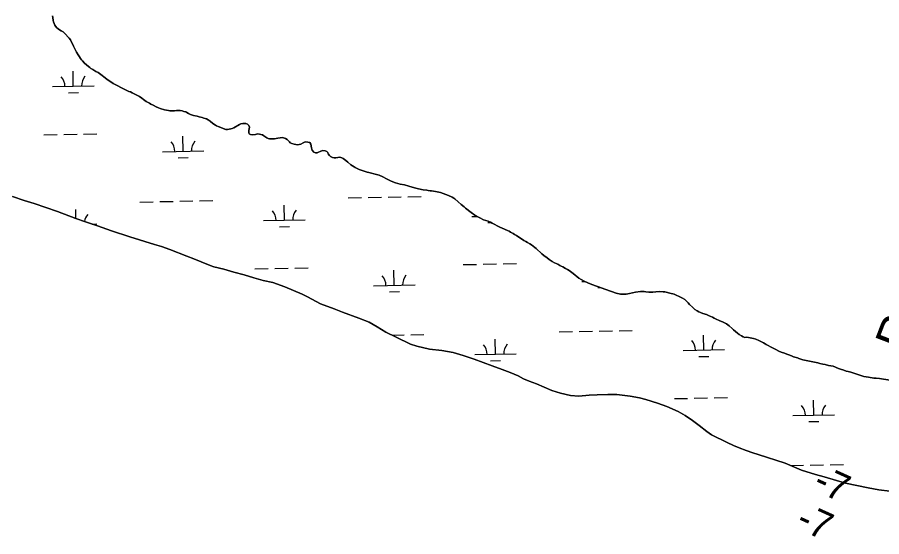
# Model space of a CAD drawing. Extents: x 3989314 to 4027622, y 243956 to 270014.
# Drawn here: x 4016981 to 4019063, y 256390 to 257641 of the extents above; entities that cross this region are included whole.
import ezdxf

# ---------------------------------------------------------------- set-up
doc = ezdxf.new("R2010")
doc.units = 0
for name, color, linetype in [('V-RIVR-EDGE', 7, 'Continuous'), ('V-RIVR-RANG', 7, 'Continuous'), ('V-RIVR-RANG-IDEN', 7, 'Continuous'), ('V-WETL-SWMP', 7, 'Continuous')]:
    doc.layers.add(name, color=color, linetype=linetype)

msp = doc.modelspace()

# ---------------------------------------------------------------- linework, layer by layer
at = {"layer": 'V-RIVR-EDGE'}
for points in [[(4017495.6, 257372.1), (4017487.8, 257370.7), (4017483.6, 257371), (4017465.3, 257377.9), (4017460.9, 257379.8), (4017458.2, 257381.2), (4017452.3, 257385.4), (4017446.1, 257390.7), (4017441.2, 257394.2), (4017436.7, 257396.4), (4017430.7, 257398.5), (4017426.4, 257399.8), (4017419.3, 257401.4), (4017414.5, 257402.7), (4017405.8, 257404.7), (4017398.5, 257406.9), (4017393.6, 257409.3), (4017389.9, 257411.5), (4017386.7, 257413), (4017382.6, 257414.5), (4017378.2, 257415.6), (4017373.6, 257416.4), (4017368.7, 257416.5), (4017364.7, 257416.2), (4017359.9, 257416.1), (4017356.3, 257415.8), (4017348.7, 257416), (4017345.6, 257416.3), (4017336, 257418.2), (4017325, 257421.6), (4017321, 257423.1), (4017315.9, 257425.7), (4017308.2, 257429.1), (4017302.9, 257431.8), (4017299.2, 257433.9), (4017296.1, 257436), (4017291.2, 257438.5), (4017285.5, 257443), (4017281.4, 257445.9), (4017275.7, 257449.9), (4017270.6, 257453), (4017257.7, 257459.5), (4017253.9, 257461.2), (4017250, 257462.7), (4017244.9, 257465), (4017234, 257470.7), (4017220.5, 257477.2), (4017212.2, 257481.6), (4017203.8, 257487.6), (4017200.3, 257489.7), (4017197, 257492.4), (4017189.3, 257497.8), (4017185.8, 257500.7), (4017175.7, 257507.7), (4017170.6, 257510.6), (4017162.9, 257515.4), (4017158.4, 257517.9), (4017155.5, 257519.8), (4017152.3, 257522.3), (4017143.2, 257530.7), (4017138.6, 257535.8), (4017136, 257538.2), (4017133, 257542.1), (4017131.1, 257545.7), (4017127.8, 257550.4), (4017124, 257557.1), (4017116.8, 257571.6), (4017109.2, 257586.4), (4017106, 257591), (4017094.9, 257603.1), (4017091.8, 257605.8), (4017087.1, 257608.7), (4017083.2, 257610.4), (4017079.3, 257612.9), (4017075.2, 257616.4), (4017071.3, 257621.8), (4017068.6, 257630.3), (4017067.8, 257633.3), (4017066.6, 257640.1), (4017066.2, 257644.9)], [(4018028.9, 257207.6), (4018019.9, 257212.3), (4018007.2, 257216.8), (4018000.3, 257218.8), (4017988.4, 257221.5), (4017978.9, 257223.1), (4017975.5, 257223.4), (4017970.8, 257224.1), (4017967.6, 257224.8), (4017958.9, 257225.6), (4017947.4, 257227.9), (4017937.9, 257230.6), (4017924.6, 257234.7), (4017913.9, 257237.4), (4017903.2, 257239.1), (4017892, 257242.2), (4017881.5, 257246.2), (4017877, 257248.7), (4017873.6, 257250.2), (4017870.3, 257252.3), (4017861.9, 257256.9), (4017852.8, 257260.7), (4017846.1, 257262.9), (4017827.7, 257267.2), (4017824.1, 257267.9), (4017821.2, 257269), (4017816.4, 257270.3), (4017804.2, 257274.8), (4017795.1, 257279), (4017792.2, 257280.7), (4017784.8, 257286.1), (4017777.1, 257292.1), (4017772.1, 257296.4), (4017766.4, 257300.7), (4017762.7, 257302.6), (4017758.3, 257303.9), (4017753.1, 257303.6), (4017748.3, 257303), (4017744.4, 257302.9), (4017740.6, 257303.6), (4017735.9, 257305.5), (4017733.1, 257308), (4017730.3, 257312), (4017728.9, 257315.1), (4017726.8, 257318.1), (4017722.9, 257319.8), (4017716.5, 257320), (4017710.9, 257318.1), (4017706.5, 257315.9), (4017703.4, 257314.7), (4017699.6, 257314.4), (4017695.3, 257316.3), (4017691.7, 257321), (4017690.5, 257323.8), (4017690, 257326.8), (4017688.1, 257335.7), (4017685.4, 257339.3), (4017680.8, 257340.4), (4017676.4, 257340.8), (4017673, 257340), (4017669.6, 257338.9), (4017663.8, 257335.7), (4017659.9, 257334.4), (4017656.1, 257333.9), (4017648.4, 257335.3), (4017642.7, 257336.9), (4017638.7, 257338.8), (4017636.4, 257340.8), (4017631.4, 257346.7), (4017627.1, 257349.4), (4017622.5, 257351), (4017619.6, 257351.4), (4017614, 257351), (4017608.9, 257349.9), (4017600.3, 257348.6), (4017591.8, 257348), (4017588.4, 257348.1), (4017585.4, 257349), (4017582.1, 257351), (4017575.2, 257356), (4017571.9, 257357.7), (4017568, 257359.2), (4017564.4, 257359.9), (4017559.8, 257360.2), (4017555, 257359.1), (4017548, 257357.9), (4017543.2, 257358.6), (4017539.9, 257360.1), (4017538.6, 257363.8), (4017538.9, 257368.7), (4017540.1, 257376.1), (4017539, 257380.3), (4017535.9, 257383.3), (4017531.8, 257385.3), (4017527.8, 257385.6), (4017524.4, 257385.4), (4017519.6, 257384.4), (4017516.4, 257382.9), (4017502.8, 257375.1), (4017498.6, 257373.2), (4017495.6, 257372.1)], [(4016969.7, 257209.2), (4016997.9, 257200.1), (4017022.1, 257193)], [(4018733.3, 256870.3), (4018729.6, 256871.8), (4018725.2, 256873.9), (4018719.8, 256877.3), (4018715.5, 256880.4), (4018706.1, 256888.8), (4018703.2, 256891.6), (4018696, 256898.2), (4018689.6, 256902.6), (4018684.6, 256905.3), (4018681.1, 256906.8), (4018671.9, 256911.4), (4018664.8, 256914.4), (4018659.5, 256916.9), (4018655.9, 256918.8), (4018647.3, 256922.6), (4018640.9, 256925.2), (4018632.7, 256928.2), (4018626.7, 256930.1), (4018622.6, 256931.8), (4018618.7, 256934.1), (4018613, 256937.7), (4018607.4, 256942.8), (4018600.4, 256949.8), (4018597.3, 256953.4), (4018594.9, 256955.9), (4018592.6, 256958.1), (4018588.9, 256961.2), (4018583.6, 256964.8), (4018578.7, 256967.3), (4018575.4, 256968.6), (4018568.1, 256971.9), (4018563, 256974.1), (4018553.1, 256976.9), (4018544.4, 256979.1), (4018541, 256979.8), (4018537, 256980.3), (4018526.9, 256980.6), (4018519.1, 256980.2), (4018511.7, 256979.6), (4018501.9, 256979.3), (4018494.8, 256979.9), (4018491, 256980.8), (4018482.3, 256981.2), (4018469.9, 256979.1), (4018456, 256976.1), (4018447.8, 256974.7), (4018441.8, 256974.1), (4018434.1, 256974.5), (4018423.4, 256977.2), (4018398.7, 256985.6), (4018378.4, 256993.1), (4018373.7, 256994.7), (4018360.6, 256999.6), (4018347.8, 257004.9), (4018339.2, 257009.5), (4018333.5, 257012.9), (4018320.2, 257024), (4018310.1, 257031.4), (4018306.2, 257033.9), (4018301.9, 257036.4), (4018295.2, 257040), (4018291.4, 257041.9), (4018287.9, 257043.4), (4018282.8, 257046.5), (4018275.1, 257050.1), (4018269.4, 257053), (4018262.6, 257057.6), (4018257.1, 257061.5), (4018249.7, 257067.5), (4018244.6, 257071.8), (4018231, 257084.3), (4018227.9, 257087), (4018219.7, 257093), (4018216, 257095.3), (4018209.9, 257098.4), (4018205.8, 257101.1), (4018201, 257103.6), (4018183.2, 257115.3), (4018178.9, 257117.8), (4018175.2, 257120.5), (4018169.1, 257123.6), (4018165.6, 257125.7), (4018162, 257127.4), (4018149.4, 257133.1), (4018143.5, 257135.5), (4018125.3, 257145.5), (4018121.1, 257147.6), (4018118.4, 257148.9), (4018115.2, 257149.8), (4018104.4, 257153.6), (4018095.1, 257157.9), (4018083.1, 257165), (4018074.7, 257171), (4018060.7, 257181.7), (4018057.2, 257185), (4018050.4, 257190.5), (4018043.2, 257196.9), (4018035, 257203.7), (4018032.4, 257205.6), (4018028.9, 257207.6)], [(4017022.1, 257193), (4017077.7, 257173.2), (4017122.1, 257156.3), (4017145.2, 257148.5), (4017174.6, 257139), (4017208, 257126.9), (4017252.4, 257112.4), (4017311.5, 257094.3), (4017328.7, 257088.8), (4017348.2, 257082.1), (4017389.4, 257065.5), (4017406.2, 257059.5), (4017423.9, 257052.2), (4017445.4, 257043.1), (4017454.5, 257039.9), (4017478.8, 257034.2), (4017502.4, 257027.6), (4017527.9, 257020.8), (4017551, 257013.6), (4017573.5, 257007.2), (4017596.5, 257002.2), (4017625.5, 256991.9), (4017667.1, 256974.2), (4017680.3, 256967.9), (4017711.1, 256951.3), (4017744.4, 256938.9), (4017764.3, 256930.8), (4017803.6, 256916.8), (4017828.8, 256907), (4017848.3, 256895.5), (4017869, 256882.8), (4017893.8, 256870.6), (4017928.4, 256854.1), (4017943.2, 256848.9), (4017974.3, 256842.3), (4018003.9, 256838.8), (4018031.3, 256833.6), (4018054.8, 256827), (4018081.3, 256817.8), (4018124.7, 256802.1), (4018149.2, 256793.4), (4018167.9, 256786.2), (4018187.6, 256777.9), (4018200.3, 256770.8), (4018213.7, 256765.2), (4018231.5, 256758.4), (4018268.3, 256742.5), (4018289.7, 256735.9), (4018313.6, 256730.3), (4018333.3, 256728.8), (4018358.5, 256730.9), (4018377.8, 256731.8), (4018403.9, 256732.7), (4018425, 256732.5), (4018457.4, 256729.1), (4018479.6, 256724.9), (4018495.3, 256720.9), (4018522.9, 256712.2), (4018545.8, 256703.6), (4018573, 256691.9), (4018589.4, 256681.9), (4018607.5, 256670.3), (4018623.9, 256658.3), (4018641.6, 256643.5), (4018652.9, 256635.4), (4018691.3, 256617.4), (4018705.9, 256609.9), (4018719.7, 256604.3), (4018736.4, 256598.3), (4018753, 256592.7), (4018765.7, 256588.8)], [(4018982.1, 256788.1), (4018977.4, 256789.3), (4018972.3, 256791.5), (4018964.3, 256793.6), (4018958.9, 256795.5), (4018945.9, 256800.7), (4018940.8, 256802.1), (4018935.3, 256803), (4018927, 256805.1), (4018921.7, 256806), (4018914.2, 256807.7), (4018909.1, 256809.1), (4018897.1, 256811.2), (4018881.5, 256814.6), (4018877.5, 256815.8), (4018873.2, 256816.7), (4018863.7, 256819.6), (4018860, 256821), (4018854.1, 256822.5), (4018850.7, 256823.6), (4018847.3, 256824.8), (4018842.1, 256827.3), (4018834.4, 256829.9), (4018828.8, 256832.3), (4018821, 256835.1), (4018815, 256837.4), (4018808, 256840.8), (4018803.1, 256843.4), (4018800.5, 256845.1), (4018784.9, 256853.5), (4018782.1, 256855.2), (4018778.4, 256857), (4018773.7, 256859.8), (4018767, 256863), (4018760, 256865.8), (4018754.7, 256867.6), (4018742.4, 256869.9), (4018738.2, 256870.5), (4018733.3, 256870.3)], [(4019082.6, 256767.4), (4019057.6, 256771), (4019049.9, 256771.8), (4019044.4, 256772.1), (4019031, 256774.4), (4019020.3, 256776.5), (4018989.1, 256786.6), (4018982.1, 256788.1)], [(4018765.7, 256588.8), (4018830.6, 256567.4), (4018870.3, 256550.4), (4018903.5, 256539.9), (4018924.3, 256534.4), (4018975.6, 256519.6), (4019030.2, 256508), (4019056, 256503.6), (4019082.7, 256500.1)]]:
    msp.add_lwpolyline(points, dxfattribs=at)
at = {"layer": 'V-WETL-SWMP'}
for p, q in [((4017116.1, 257475), (4017115.4, 257511)), ((4017066.1, 257474), (4017166.1, 257476)), ((4017104.4, 257459.3), (4017128.4, 257459.8)), ((4017045, 257358.1), (4017077, 257358.8)), ((4017093, 257359.1), (4017125, 257359.7)), ((4017141, 257360), (4017173, 257360.7)), ((4017380.7, 257318.4), (4017380, 257354.4)), ((4017330.7, 257317.4), (4017430.7, 257319.4)), ((4017369, 257302.7), (4017393, 257303.2)), ((4017276.3, 257196.2), (4017308.3, 257196.8)), ((4017324.3, 257197.2), (4017356.3, 257197.8)), ((4017372.3, 257198.1), (4017404.2, 257198.8)), ((4017420.2, 257199.1), (4017452.2, 257199.7)), ((4017778.1, 257206.2), (4017810.1, 257206.8)), ((4017826.1, 257207.2), (4017858.1, 257207.8)), ((4017874.1, 257208.1), (4017906.1, 257208.8)), ((4017922, 257209.1), (4017954, 257209.7)), ((4017122.4, 257156.2), (4017122, 257178.4)), ((4017624.5, 257152.4), (4017623.8, 257188.4)), ((4018076.3, 257161.4), (4018088.7, 257161.6)), ((4017161.7, 257143.2), (4017172.7, 257143.4)), ((4017574.5, 257151.4), (4017674.5, 257153.4)), ((4017612.8, 257136.7), (4017636.8, 257137.2)), ((4018114.6, 257146.7), (4018122.6, 257146.9)), ((4017553.4, 257035.5), (4017585.4, 257036.2)), ((4017601.4, 257036.5), (4017633.4, 257037.1)), ((4017649.4, 257037.4), (4017681.4, 257038.1)), ((4017889.1, 256995.8), (4017888.4, 257031.8)), ((4018055.2, 257045.5), (4018087.2, 257046.2)), ((4018103.2, 257046.5), (4018135.2, 257047.1)), ((4018151.2, 257047.4), (4018183.2, 257048.1)), ((4017839.1, 256994.8), (4017939.1, 256996.8)), ((4018341, 257004.8), (4018347.8, 257004.9)), ((4018379.3, 256990.1), (4018386.2, 256990.2)), ((4017877.4, 256980.1), (4017901.4, 256980.6)), ((4018286.5, 256883.6), (4018318.5, 256884.2)), ((4018334.5, 256884.6), (4018366.5, 256885.2)), ((4018382.5, 256885.5), (4018414.5, 256886.1)), ((4018430.5, 256886.5), (4018462.5, 256887.1)), ((4017883.7, 256875.6), (4017912.7, 256876.1)), ((4017928.7, 256876.5), (4017960.7, 256877.1)), ((4018133, 256829.8), (4018132.2, 256865.8)), ((4018634.8, 256839.8), (4018634.1, 256875.8)), ((4018083, 256828.8), (4018183, 256830.8)), ((4018584.8, 256838.8), (4018684.8, 256840.8)), ((4018623.1, 256824.1), (4018647.1, 256824.6)), ((4018121.3, 256814.1), (4018145.3, 256814.6)), ((4018563.7, 256722.9), (4018595.7, 256723.6)), ((4018611.7, 256723.9), (4018643.7, 256724.5)), ((4018659.7, 256724.8), (4018691.7, 256725.5)), ((4018899.4, 256683.2), (4018898.7, 256719.2)), ((4018849.4, 256682.2), (4018949.4, 256684.2)), ((4018887.7, 256667.5), (4018911.7, 256668)), ((4018843.4, 256562), (4018874.9, 256562.6)), ((4018890.9, 256562.9), (4018922.9, 256563.5)), ((4018938.9, 256563.9), (4018970.9, 256564.5))]:
    msp.add_line(p, q, dxfattribs=at)
for points in [[(4017066.2, 257644.9), (4017066.6, 257640.1), (4017067.9, 257633.3), (4017068.6, 257630.3), (4017071.3, 257621.8), (4017075.2, 257616.4), (4017079.3, 257612.9), (4017083.2, 257610.4), (4017087.1, 257608.7), (4017091.8, 257605.8), (4017094.9, 257603.1), (4017106, 257591), (4017109.2, 257586.4), (4017116.8, 257571.6), (4017124, 257557.1), (4017127.8, 257550.4), (4017131.1, 257545.7), (4017133, 257542.1), (4017136, 257538.2), (4017138.6, 257535.8), (4017143.2, 257530.7), (4017152.3, 257522.3), (4017155.5, 257519.8), (4017158.4, 257517.9), (4017162.9, 257515.4), (4017170.6, 257510.6), (4017175.7, 257507.7), (4017185.8, 257500.7), (4017189.3, 257497.8), (4017197, 257492.4), (4017200.3, 257489.7), (4017203.8, 257487.6), (4017212.2, 257481.6), (4017220.5, 257477.2), (4017234, 257470.7), (4017244.9, 257465), (4017250, 257462.7), (4017253.9, 257461.2), (4017257.7, 257459.5), (4017270.6, 257453), (4017275.7, 257449.9)], [(4017275.7, 257449.9), (4017281.4, 257445.9), (4017285.5, 257443), (4017291.2, 257438.5), (4017296.1, 257436), (4017299.2, 257433.9), (4017302.9, 257431.8), (4017308.2, 257429.1), (4017315.9, 257425.7), (4017321, 257423.1), (4017325, 257421.6), (4017336, 257418.2), (4017345.6, 257416.3), (4017348.7, 257416), (4017356.3, 257415.8), (4017359.9, 257416.1), (4017364.7, 257416.2), (4017368.7, 257416.5), (4017373.6, 257416.4), (4017378.2, 257415.6), (4017382.6, 257414.5), (4017386.7, 257413), (4017389.9, 257411.5), (4017393.6, 257409.3), (4017398.5, 257406.9), (4017405.8, 257404.7), (4017414.5, 257402.7), (4017419.3, 257401.4), (4017426.4, 257399.8), (4017430.7, 257398.5), (4017436.7, 257396.4), (4017441.2, 257394.2), (4017446.1, 257390.7), (4017452.3, 257385.4), (4017458.2, 257381.2), (4017460.9, 257379.8), (4017465.3, 257377.9), (4017483.6, 257371), (4017487.8, 257370.7), (4017495.6, 257372.1), (4017498.6, 257373.2), (4017502.8, 257375.1), (4017516.4, 257382.9), (4017519.6, 257384.4), (4017524.4, 257385.4), (4017527.8, 257385.6), (4017531.8, 257385.3), (4017535.9, 257383.3), (4017539, 257380.3), (4017540.1, 257376.1), (4017538.9, 257368.7), (4017538.6, 257363.8), (4017539.9, 257360.1), (4017543.2, 257358.6), (4017548, 257357.9), (4017555, 257359.1), (4017559.8, 257360.2), (4017564.4, 257359.9), (4017568, 257359.2), (4017571.9, 257357.7), (4017575.2, 257356), (4017582.1, 257351), (4017585.4, 257349), (4017588.4, 257348.1), (4017591.8, 257348), (4017600.3, 257348.6), (4017609, 257349.9), (4017614, 257351), (4017619.5, 257351.4), (4017622.5, 257351), (4017627.1, 257349.4), (4017631.4, 257346.7), (4017636.4, 257340.8), (4017638.7, 257338.8), (4017642.7, 257336.9), (4017648.4, 257335.3), (4017656.1, 257333.9), (4017659.9, 257334.4), (4017663.8, 257335.7), (4017669.6, 257338.9), (4017673, 257340), (4017676.4, 257340.8), (4017680.8, 257340.4), (4017685.4, 257339.3), (4017688.1, 257335.7), (4017690, 257326.8), (4017690.5, 257323.8), (4017691.7, 257321), (4017695.3, 257316.3), (4017699.6, 257314.4), (4017703.4, 257314.7), (4017706.5, 257315.9), (4017710.9, 257318.1), (4017716.5, 257320), (4017722.9, 257319.8), (4017726.8, 257318.1), (4017728.9, 257315.1), (4017730.3, 257312), (4017733.1, 257308), (4017735.9, 257305.5), (4017740.6, 257303.6)], [(4017740.6, 257303.6), (4017744.4, 257302.9), (4017748.3, 257303), (4017753.1, 257303.6), (4017758.3, 257303.9), (4017762.7, 257302.6), (4017766.4, 257300.7), (4017772.1, 257296.4), (4017777.1, 257292.1), (4017784.8, 257286.1), (4017792.2, 257280.7), (4017795.1, 257279), (4017804.2, 257274.8), (4017816.4, 257270.3), (4017821.2, 257269), (4017824.1, 257267.9), (4017827.7, 257267.2), (4017846.1, 257262.9), (4017852.8, 257260.7), (4017861.9, 257256.9), (4017870.3, 257252.3), (4017873.6, 257250.2), (4017877, 257248.7), (4017881.5, 257246.2), (4017892, 257242.2), (4017903.2, 257239.1), (4017913.9, 257237.4), (4017924.6, 257234.7), (4017937.9, 257230.6), (4017947.4, 257227.9), (4017958.9, 257225.6), (4017967.6, 257224.8), (4017970.8, 257224.1), (4017975.5, 257223.4), (4017978.9, 257223.1), (4017988.4, 257221.5), (4018000.3, 257218.8), (4018007.2, 257216.8), (4018019.9, 257212.3), (4018028.9, 257207.6), (4018032.4, 257205.6), (4018035, 257203.7), (4018043.2, 257196.9), (4018050.4, 257190.5), (4018057.2, 257185), (4018060.7, 257181.7), (4018074.7, 257171), (4018083.1, 257165), (4018095.1, 257157.9), (4018104.4, 257153.6), (4018115.2, 257149.8), (4018118.4, 257148.9), (4018121.1, 257147.6), (4018125.3, 257145.5), (4018143.5, 257135.5), (4018149.4, 257133.1), (4018162, 257127.4), (4018165.6, 257125.7), (4018169.1, 257123.6), (4018175.2, 257120.5), (4018178.9, 257117.8), (4018183.2, 257115.3), (4018201, 257103.6), (4018205.8, 257101.1), (4018209.9, 257098.4), (4018216, 257095.3), (4018219.7, 257093), (4018227.9, 257087), (4018231, 257084.3), (4018244.6, 257071.8), (4018249.7, 257067.5), (4018257.1, 257061.5), (4018262.6, 257057.6), (4018269.4, 257053), (4018275.1, 257050.1), (4018282.8, 257046.5), (4018287.9, 257043.4), (4018291.4, 257041.9), (4018295.2, 257040), (4018301.9, 257036.4), (4018306.2, 257033.9), (4018310.1, 257031.4), (4018320.2, 257024), (4018333.5, 257012.9), (4018339.2, 257009.5), (4018347.8, 257004.9), (4018360.6, 256999.6), (4018373.7, 256994.7), (4018378.4, 256993.1), (4018398.7, 256985.6), (4018423.4, 256977.2), (4018434.1, 256974.5), (4018441.8, 256974.1), (4018447.8, 256974.7), (4018456, 256976.1), (4018469.9, 256979.1), (4018482.3, 256981.2), (4018491, 256980.8), (4018494.8, 256979.9), (4018501.9, 256979.3), (4018511.7, 256979.6)], [(4019082.7, 256500.1), (4019056, 256503.6), (4019030.2, 256508), (4018975.6, 256519.6), (4018924.3, 256534.4), (4018903.5, 256539.9), (4018870.3, 256550.4), (4018830.6, 256567.4), (4018765.7, 256588.8), (4018753, 256592.7), (4018736.4, 256598.3), (4018719.7, 256604.3), (4018705.9, 256609.9), (4018691.3, 256617.4), (4018652.9, 256635.4), (4018641.6, 256643.5), (4018623.9, 256658.3), (4018607.5, 256670.3), (4018589.4, 256681.9), (4018573, 256691.9), (4018545.8, 256703.6), (4018522.9, 256712.2), (4018495.3, 256720.9), (4018479.6, 256724.9), (4018457.4, 256729.1), (4018425, 256732.5), (4018403.9, 256732.7), (4018377.8, 256731.8), (4018358.5, 256730.9), (4018333.3, 256728.8), (4018313.6, 256730.3), (4018289.7, 256735.9), (4018268.3, 256742.5), (4018231.5, 256758.4), (4018213.7, 256765.2), (4018200.3, 256770.8), (4018187.6, 256777.9), (4018167.9, 256786.2), (4018149.2, 256793.4), (4018124.7, 256802.1), (4018081.3, 256817.8), (4018054.8, 256827), (4018031.3, 256833.6), (4018003.9, 256838.8), (4017974.3, 256842.3), (4017943.2, 256848.9), (4017928.4, 256854.1), (4017893.8, 256870.6), (4017869, 256882.8), (4017848.3, 256895.5), (4017828.8, 256907), (4017803.6, 256916.8), (4017764.3, 256930.8), (4017744.4, 256938.9), (4017711.1, 256951.3), (4017680.3, 256967.9), (4017667.1, 256974.2), (4017625.5, 256991.9), (4017596.5, 257002.2), (4017573.5, 257007.2), (4017551, 257013.6), (4017527.9, 257020.8), (4017502.4, 257027.6), (4017478.8, 257034.2), (4017454.5, 257039.9), (4017445.4, 257043.1), (4017423.9, 257052.2), (4017406.2, 257059.5), (4017389.4, 257065.5), (4017348.2, 257082.1), (4017328.7, 257088.8), (4017311.5, 257094.3), (4017252.4, 257112.4), (4017208, 257126.9), (4017174.6, 257139), (4017145.2, 257148.5), (4017122.1, 257156.3), (4017077.7, 257173.2), (4017022.1, 257193), (4016998, 257200.1), (4016969.7, 257209.2)], [(4018511.7, 256979.6), (4018519.1, 256980.2), (4018526.9, 256980.6), (4018537, 256980.3), (4018541, 256979.8), (4018544.4, 256979.1), (4018553.1, 256976.9), (4018563, 256974.1), (4018568.1, 256971.9), (4018575.4, 256968.6), (4018578.7, 256967.3), (4018583.6, 256964.8), (4018588.9, 256961.2), (4018592.6, 256958.1), (4018594.9, 256955.9), (4018597.3, 256953.4), (4018600.4, 256949.8), (4018607.4, 256942.8), (4018613, 256937.7), (4018618.7, 256934.1), (4018622.6, 256931.8), (4018626.7, 256930.1), (4018632.7, 256928.2), (4018640.9, 256925.2), (4018647.3, 256922.6), (4018655.9, 256918.8), (4018659.5, 256916.9), (4018664.8, 256914.4), (4018671.9, 256911.4), (4018681.1, 256906.8), (4018684.6, 256905.3), (4018689.6, 256902.6), (4018696, 256898.2), (4018703.2, 256891.6), (4018706.1, 256888.8), (4018715.5, 256880.4), (4018719.8, 256877.3), (4018725.2, 256873.9), (4018729.6, 256871.8), (4018733.3, 256870.3), (4018738.2, 256870.5), (4018742.4, 256869.9), (4018754.7, 256867.6), (4018760, 256865.8), (4018767, 256863), (4018773.7, 256859.8), (4018778.4, 256857), (4018782.1, 256855.2), (4018784.9, 256853.5), (4018800.5, 256845.1), (4018803.1, 256843.4), (4018808, 256840.8), (4018815, 256837.4), (4018821, 256835.1), (4018828.8, 256832.3), (4018834.4, 256829.9), (4018842.1, 256827.3), (4018847.3, 256824.8), (4018850.7, 256823.6), (4018854.1, 256822.5), (4018860, 256821), (4018863.7, 256819.6), (4018873.2, 256816.7), (4018877.5, 256815.8), (4018881.5, 256814.6), (4018897.1, 256811.2), (4018909.1, 256809.1), (4018914.2, 256807.7), (4018921.7, 256806), (4018927, 256805.1), (4018935.3, 256803), (4018940.8, 256802.1), (4018945.9, 256800.7), (4018958.9, 256795.5), (4018964.3, 256793.6), (4018972.3, 256791.5), (4018977.4, 256789.3), (4018982.1, 256788.1), (4018989.1, 256786.6), (4019020.3, 256776.5), (4019031, 256774.4), (4019044.4, 256772.1), (4019049.9, 256771.8), (4019057.6, 256771), (4019082.6, 256767.4)]]:
    msp.add_lwpolyline(points, dxfattribs=at)
for centre, start, end in [((4017060.8, 257474.4), 0.3699, 41.9135), ((4017171.3, 257476.6), 140.3699, 181.9135), ((4017325.5, 257317.8), 0.3699, 41.9135), ((4017435.9, 257320), 140.3699, 181.9135), ((4017569.3, 257151.8), 0.3699, 41.9135), ((4017679.7, 257154), 140.3699, 181.9135), ((4017177.9, 257144), 140.3699, 171.4238), ((4017833.9, 256995.1), 0.3699, 41.9135), ((4017944.4, 256997.3), 140.3699, 181.9135), ((4018579.5, 256839.2), 0.3699, 41.9135), ((4018690, 256841.4), 140.3699, 181.9135), ((4018077.7, 256829.2), 0.3699, 41.9135), ((4018188.2, 256831.4), 140.3699, 181.9135), ((4018844.1, 256682.5), 0.3699, 41.9135), ((4018954.6, 256684.7), 140.3699, 181.9135)]:
    msp.add_arc(centre, 35.2, start, end, dxfattribs=at)

# ---------------------------------------------------------------- texts
at = {"layer": 'V-RIVR-RANG'}
for p in [(4018894.5, 256504.3), (4018853.3, 256412.7)]:
    msp.add_text('-7', height=67, rotation=335.6714, dxfattribs=at).set_placement(p)
at = {"layer": 'V-RIVR-RANG-IDEN'}
msp.add_text('R-14.5', height=83, rotation=69.0841, dxfattribs=at).set_placement((4019122.8, 256831.3))

doc.saveas('drawing.dxf')
